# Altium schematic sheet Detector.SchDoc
size A4
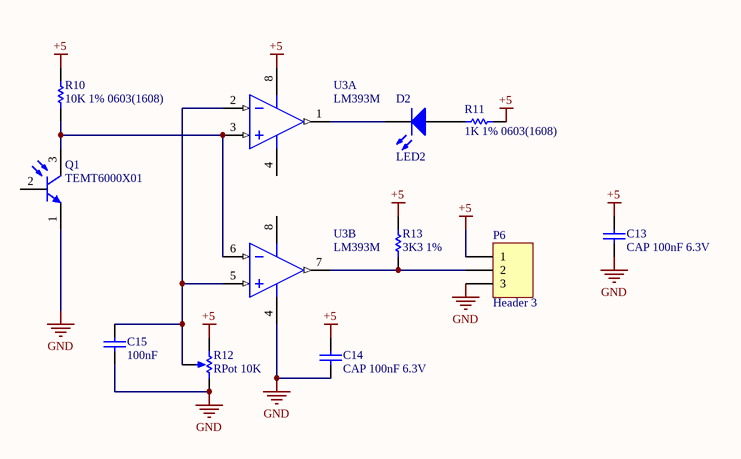
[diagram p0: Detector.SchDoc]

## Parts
C13  CAP 100nF 6.3V  [CAPC0603(1608)100_N]
C14  CAP 100nF 6.3V  [CAPC0603(1608)100_N]
C15  100nF  [CAPC0603(1608)100_N]
D2  LED2  [0603]
P6  Header 3  [PH2.0-WS-3P]
Q1  TEMT6000X01  [VSIL-TEMT6000X01_V]
R10  10K 1% 0603(1608)  [RESC0603(1608)_N]
R11  1K 1% 0603(1608)  [RESC0603(1608)_N]
R12  RPot 10K  [BOUR-3362P]
R13  3K3 1%  [RESC0603(1608)_N]
U3  LM393M  [M08A_N]  (parts A,B of 2)

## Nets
+5: C13.2 C14.2 P6.1 R10.2 R11.2 R12.1(TOP) R13.2 U3.8(V+)
GND: C13.1 C14.1 C15.1 P6.3 Q1.1(E) R12.3(BOT) U3.4(GND)
NetC15_2: C15.2 R12.2(TAP) U3.2(INA-) U3.5(INB+)
NetD2_1: D2.1(A) R11.1
NetD2_2: D2.2(K) U3.1(OUTA)
NetP6_2: P6.2 R13.1 U3.7(OUTB)
NetQ1_3: Q1.3(C) R10.1 U3.3(INA+) U3.6(INB-)

Not connected (* = marked no-connect by the designer): Q1 2(B)

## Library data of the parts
C13-C15 = CMP-1035-02576-1: CAP 100nF 6.3V ±10% 0603 (1608 Metric) Thickness 1mm SMD; Tolerance: Â±10%; Case-Metric: 1608; Case-EIA: 0603
D2 = LED2: Typical RED, GREEN, YELLOW, AMBER GaAs LED
P6 = Header 3: Header, 3-Pin
Q1 = CMP-1666-00035-1: Ambient Light Sensor / , 100 mW, -40 to 100 degC, 3-Pin SMD, RoHS, Tape and Reel; Nominal Vf: 2 V; Luminous Intensity: 54 mcd; Forward Current: 20 mA; Viewing Angle: 130 degrees; Lens Style: Diffused; Power Rating: 75 mW; Colour: Red; Case\Package: 0603
R10 = CMP-1012-00623-1: 10K 0.1W 1% 0603 (1608 Metric)  SMD; Value: 10000.00 Ohm; Case-EIA: 0603; Case-Metric: 1608
R11 = CMP-1012-00510-1: 1K 0.1W 1% 0603 (1608 Metric)  SMD; Case-Metric: 1608; Case-EIA: 0603; Value: 1000.00 Ohm
R12 = RPot: Potentiometer; Sim Note: Enter the Resistance value and the set point into parameter fields.; Set Position: 0.5
R13 = CMP-1012-00567-1: 3K3 0.1W 1% 0603 (1608 Metric)  SMD; Case-Metric: 1608; Value: 3300.00 Ohm; Case-EIA: 0603
U3 = CMP-0055-00682-2: Low Power Low Offset Voltage Dual Comparator, 8-pin Narrow SOIC; Manufacturer: National Semiconductor; CompType: Amplifiers; PackageTopMarking: NSZXTT*LM*393M; PowerWise: N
